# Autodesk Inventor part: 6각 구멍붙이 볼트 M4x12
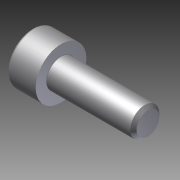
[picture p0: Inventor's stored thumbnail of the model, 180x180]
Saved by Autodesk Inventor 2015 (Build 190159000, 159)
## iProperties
Created: 2026-04
Part Number: 6각 구멍붙이 볼트 M4x12
Material: 일반
Document SubType Name: Modeling
Designer: User
Density: 1 g/cm^3
Appearance: 기본값
Author: User
Author: jhkim
Description: 6각머리 태핑 나사
Creation Date: 2026-04-06
Sending System: Autodesk Inventor 2027
Preprocessor: ST-DEVELOPER v20.1
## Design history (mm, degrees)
node "6각 구멍붙이 볼트 M4x121"
body "Solid1"
node "기준1"
